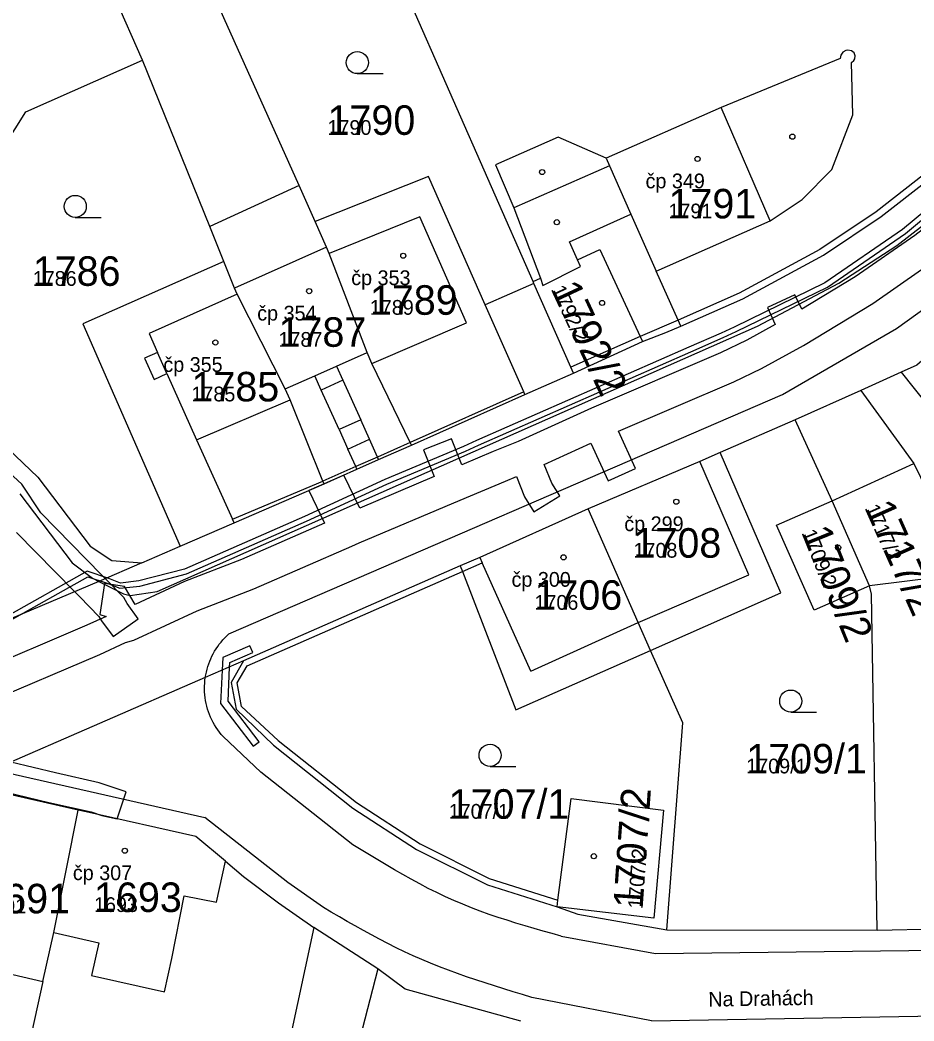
# Model space of a CAD drawing. Extents: x -763628 to -761565, y -976033 to -973833.
# Drawn here: x -762525.4 to -762464.8, y -975069 to -975001.2 of the extents above; entities that cross this region are included whole.
import ezdxf

# ---------------------------------------------------------------- set-up
doc = ezdxf.new("R2010")
doc.units = 0
for name, color, linetype in [('KN_cisla parcel 1000', 7, 'Continuous'), ('KN_cisla parcel 500', 7, 'Continuous'), ('KN_cisla popisna 500', 7, 'Continuous'), ('KN_hranice parcel', 7, 'Continuous'), ('KN_popisy', 7, 'Continuous'), ('KN_vecna bremena', 7, 'Continuous'), ('KN_vnitrni kresba parcel', 7, 'Continuous'), ('KN_znacky budov', 7, 'Continuous'), ('KN_znacky kultur', 7, 'Continuous')]:
    doc.layers.add(name, color=color, linetype=linetype)

msp = doc.modelspace()

# ---------------------------------------------------------------- linework, layer by layer
at = {"layer": 'KN_hranice parcel'}
for p, q in [((-762517.1, -975003.93), (-762523.87, -974988.55)), ((-762490.64, -975018.92), (-762501.97, -974993.16)), ((-762512.55, -975015.2), (-762517.1, -975003.93)), ((-762506.5, -975012.42), (-762512.55, -975015.2)), ((-762505.4, -975014.87), (-762506.5, -975012.42)), ((-762511.6, -975017.57), (-762512.55, -975015.2)), ((-762490.64, -975018.92), (-762490.15, -975018.71)), ((-762490.58, -975019.05), (-762490.64, -975018.92)), ((-762487.91, -975025.13), (-762483.23, -975022.98)), ((-762465.7, -975025.07), (-762468.44, -975026.31)), ((-762468.44, -975026.31), (-762472.88, -975028.3)), ((-762472.88, -975028.3), (-762477.97, -975030.52)), ((-762470.38, -975033.78), (-762472.88, -975028.3)), ((-762467.84, -975039.55), (-762470.38, -975033.78)), ((-762517.15, -975038), (-762514.55, -975036.87)), ((-762495.58, -975038.2), (-762510.26, -975044.64)), ((-762461.2, -975038.71), (-762467.84, -975039.55)), ((-762523.11, -975063.05), (-762521.46, -975054.75)), ((-762505.49, -975062.7), (-762510.94, -975087.94)), ((-762501.17, -975065.5), (-762505.49, -975062.7)), ((-762481.58, -975062.85), (-762467.32, -975062.87)), ((-762467.32, -975062.87), (-762452.41, -975062.54)), ((-762523.85, -975066.37), (-762523.11, -975063.05)), ((-762523.85, -975066.37), (-762527.5, -975082.74))]:
    msp.add_line(p, q, dxfattribs=at)
for points in [[(-762506.5, -975012.42), (-762513, -974997.92), (-762501.97, -974993.16)], [(-762480.64, -975021.95), (-762476.44, -975020.11), (-762470.96, -975017.13), (-762467.07, -975014.52), (-762463.89, -975012.05), (-762460.54, -975009.19), (-762458.45, -975006.67), (-762454.5, -975000.38)], [(-762469.83, -975003.81), (-762477.89, -975007.14), (-762485.7, -975010.56), (-762488.95, -975009.15), (-762493.19, -975011.01), (-762491.95, -975013.93), (-762490.15, -975018.71)], [(-762469.07, -975004.08), (-762468.906, -975003.949), (-762468.842, -975003.836), (-762468.816, -975003.627), (-762468.89, -975003.43), (-762469.079, -975003.295), (-762469.307, -975003.252), (-762469.453, -975003.276), (-762469.654, -975003.392), (-762469.788, -975003.582), (-762469.83, -975003.81)], [(-762534.93, -975023.19), (-762525.01, -975007.43), (-762517.1, -975003.93)], [(-762480.64, -975021.95), (-762480.82, -975021.54), (-762482.31, -975018.23), (-762474.57, -975014.82), (-762472.41, -975013.37), (-762470.39, -975011.34), (-762468.98, -975007.63), (-762469.07, -975004.08)], [(-762490.58, -975019.05), (-762493.89, -975020.51), (-762497.72, -975011.81), (-762505.4, -975014.87)], [(-762498.88, -975030.01), (-762498.97, -975029.83), (-762501.56, -975024.48), (-762501.89, -975023.74), (-762504.46, -975017.02), (-762504.63, -975016.6), (-762505.4, -975014.87)], [(-762490.15, -975018.71), (-762489.97, -975019.19), (-762487.42, -975017.92), (-762487.63, -975017.46), (-762486.13, -975016.76), (-762483.38, -975022.66), (-762483.23, -975022.98)], [(-762511.6, -975017.57), (-762521.15, -975021.79), (-762514.55, -975036.87)], [(-762504.8, -975032.64), (-762504.88, -975032.46), (-762507.1, -975026.94), (-762507.43, -975026.2), (-762510.68, -975019.79), (-762510.87, -975019.38), (-762511.6, -975017.57)], [(-762487.91, -975025.13), (-762488.09, -975024.72), (-762490.58, -975019.05)], [(-762458.55, -975019.31), (-762464.65, -975024.6), (-762465.7, -975025.07)], [(-762483.23, -975022.98), (-762481.65, -975022.39), (-762480.64, -975021.95)], [(-762534.93, -975023.19), (-762529.25, -975027.37), (-762524.19, -975032.19), (-762520.65, -975036.86), (-762519.19, -975037.83), (-762517.15, -975038)], [(-762498.88, -975030.01), (-762491.19, -975026.59), (-762487.91, -975025.13)], [(-762465.7, -975025.07), (-762460.23, -975031.94), (-762459.3, -975033.11), (-762458.98, -975033.52), (-762457.78, -975032.48), (-762451.59, -975027.12)], [(-762468.44, -975026.31), (-762464.84, -975031.25), (-762461.2, -975038.71)], [(-762504.8, -975032.64), (-762502.58, -975031.65), (-762501.11, -975030.99), (-762498.88, -975030.01)], [(-762477.97, -975030.52), (-762479.34, -975031.12), (-762486.91, -975034.34)], [(-762482.69, -975043.92), (-762473.86, -975040.03), (-762477.97, -975030.52)], [(-762514.55, -975036.87), (-762510.89, -975035.28), (-762504.8, -975032.64)], [(-762486.91, -975034.34), (-762494.25, -975037.62), (-762495.58, -975038.2)], [(-762482.69, -975043.92), (-762483.53, -975042.04), (-762486.91, -975034.34)], [(-762467.84, -975039.55), (-762471.6, -975041.2), (-762474.14, -975035.44), (-762470.38, -975033.78)], [(-762517.15, -975038), (-762520.07, -975039.25), (-762525.98, -975041.77), (-762528.89, -975043.05)], [(-762495.58, -975038.2), (-762495.42, -975038.57), (-762491.81, -975047.94), (-762482.69, -975043.92)], [(-762467.32, -975062.87), (-762467.71, -975040.11), (-762467.84, -975039.55)], [(-762481.58, -975062.85), (-762480.49, -975048.83), (-762482.69, -975043.92)], [(-762510.26, -975044.64), (-762512.85, -975045.76), (-762527.2, -975052), (-762529.39, -975052.95)], [(-762510.26, -975044.64), (-762511.1, -975046.1), (-762510.76, -975047.9), (-762508.23, -975050.35), (-762502.86, -975054.62), (-762498.54, -975057.41), (-762493.74, -975059.82), (-762489.02, -975061.3), (-762487.6, -975061.79), (-762481.58, -975062.85)], [(-762521.46, -975054.75), (-762529.29, -975052.97), (-762529.39, -975052.95)], [(-762489.02, -975061.3), (-762488.96, -975060.85), (-762488.06, -975053.96), (-762481.8, -975054.75), (-762482.47, -975062.06), (-762489.02, -975061.3)], [(-762533.02, -975054.55), (-762533.31, -975056.34), (-762530.12, -975057), (-762531, -975061.31), (-762531.75, -975063.61), (-762527.39, -975064.54), (-762527.66, -975065.47), (-762523.85, -975066.37)], [(-762511.48, -975058.21), (-762513.48, -975056.53), (-762520.93, -975054.87), (-762521.46, -975054.75)], [(-762523.11, -975063.05), (-762520.07, -975063.73), (-762520.57, -975065.95), (-762515.62, -975067.05), (-762515.12, -975064.81), (-762514.28, -975060.55), (-762512.09, -975060.99), (-762511.48, -975058.21)], [(-762511.48, -975058.21), (-762510.25, -975059.24), (-762507.9, -975061.04), (-762505.49, -975062.7)], [(-762501.17, -975065.5), (-762502.4, -975070.31), (-762500.43, -975070.85), (-762501.58, -975075.02), (-762493.66, -975077.17)], [(-762491.47, -975069.04), (-762499.31, -975066.88), (-762501.17, -975065.5)]]:
    msp.add_lwpolyline(points, dxfattribs=at)
at = {"layer": 'KN_vecna bremena'}
for points in [[(-762447.96, -974992.32), (-762452.51, -975001.43), (-762454.75, -975004.97), (-762459.16, -975010.04), (-762465.61, -975015.4), (-762470.88, -975019.02), (-762477.02, -975022.01), (-762477.9, -975022.43), (-762480.09, -975023.37), (-762494.48, -975029.7), (-762495.36, -975030.1), (-762500.68, -975032.35), (-762506.13, -975034.84), (-762514.25, -975038.42), (-762517.35, -975039.22), (-762518.59, -975039.37), (-762519.38, -975039.05), (-762520.85, -975038.55), (-762526.38, -975041.67)], [(-762526.12, -975041.91), (-762520.81, -975038.93), (-762519.5, -975039.37), (-762518.63, -975039.71), (-762517.29, -975039.56), (-762514.13, -975038.74), (-762505.99, -975035.16), (-762500.54, -975032.67), (-762495.22, -975030.42), (-762494.34, -975030.02), (-762479.95, -975023.69), (-762477.76, -975022.73), (-762476.88, -975022.31), (-762470.7, -975019.32), (-762465.41, -975015.68), (-762458.92, -975010.28), (-762454.47, -975005.17), (-762452.21, -975001.59), (-762447.66, -974992.46)], [(-762451.11, -975001.14), (-762453.78, -975005.44), (-762456.48, -975008.62), (-762459.6, -975011.82), (-762464.78, -975015.8), (-762468.81, -975018.6), (-762472.44, -975020.8), (-762472.9, -975019.82), (-762474.76, -975020.68), (-762474.23, -975021.83), (-762476.16, -975022.89), (-762477.95, -975023.76), (-762486.68, -975027.5), (-762491.66, -975029.76), (-762493.35, -975030.45), (-762495.46, -975031.34), (-762496.16, -975029.58), (-762498.06, -975030.34), (-762497.35, -975032.15), (-762502.38, -975034.28), (-762503.46, -975032.04), (-762504.8, -975032.64), (-762505.83, -975033.08), (-762504.77, -975035.31)], [(-762527.76, -975047.49), (-762520, -975044.19), (-762518.25, -975043.39), (-762517.68, -975043.23), (-762513.39, -975041.24), (-762509.57, -975039.76), (-762502.93, -975036.87), (-762502.43, -975036.64), (-762495.59, -975033.74), (-762492.52, -975032.45), (-762491.77, -975032.14), (-762491.22, -975033.51), (-762490.58, -975034.54), (-762488.84, -975033.46), (-762489.38, -975032.58), (-762489.89, -975031.33), (-762486.72, -975029.89), (-762485.56, -975032.44), (-762483.7, -975031.6), (-762484.85, -975029.07), (-762477.05, -975025.72), (-762475.17, -975024.81), (-762472.33, -975023.26), (-762467.63, -975020.42), (-762464.33, -975018.12)], [(-762525.63, -975035.93), (-762521.7, -975039.94), (-762521.36, -975040.29), (-762520.06, -975041.62), (-762519.88, -975041.93), (-762519.1, -975042.98), (-762517.4, -975041.78), (-762518.14, -975040.75), (-762518.38, -975040.34), (-762519.63, -975039.06), (-762519.86, -975038.83), (-762523.99, -975034.61), (-762525.27, -975032.65), (-762530.21, -975028.14)], [(-762504.77, -975035.31), (-762510.39, -975037.76), (-762514.25, -975039.26), (-762517.59, -975040.81), (-762518.32, -975039.6), (-762519.67, -975039.4), (-762519.99, -975041.48), (-762519.57, -975041.62), (-762520.88, -975042.21), (-762528.6, -975045.51)], [(-762529.16, -975052.85), (-762523.45, -975054.22), (-762520.59, -975054.87), (-762519.86, -975055.11), (-762518.81, -975055.34), (-762518.2, -975053.5), (-762520.05, -975052.89), (-762522.99, -975052.22), (-762526.03, -975051.49)]]:
    msp.add_lwpolyline(points, dxfattribs=at)
msp.add_lwpolyline([(-762509.61, -975050.42), (-762509.21, -975050.12), (-762511.31, -975047.36), (-762511.2, -975045.05), (-762511.19, -975044.74), (-762509.64, -975044.07), (-762509.84, -975043.61), (-762511.67, -975044.4), (-762511.71, -975045.27), (-762511.81, -975047.52)], close=True, dxfattribs=at)
at = {"layer": 'KN_vnitrni kresba parcel'}
for p, q in [((-762474.57, -975014.82), (-762477.89, -975007.14)), ((-762485.7, -975010.56), (-762485.46, -975011.09)), ((-762485.46, -975011.09), (-762491.95, -975013.93)), ((-762485.46, -975011.09), (-762484.02, -975014.36)), ((-762464.19, -975011.7), (-762467.4, -975014.21)), ((-762498.31, -975014.55), (-762504.46, -975017.02)), ((-762495.15, -975021.73), (-762498.31, -975014.55)), ((-762488.17, -975016.23), (-762484.02, -975014.36)), ((-762484.02, -975014.36), (-762482.31, -975018.23)), ((-762467.4, -975014.21), (-762471.21, -975016.76)), ((-762466, -975016.49), (-762462.82, -975014.02)), ((-762504.63, -975016.6), (-762510.87, -975019.38)), ((-762487.63, -975017.46), (-762488.17, -975016.23)), ((-762469.92, -975019.04), (-762466, -975016.49)), ((-762471.21, -975016.76), (-762476.67, -975019.72)), ((-762466.01, -975022.1), (-762459.57, -975017.44)), ((-762475.44, -975021.95), (-762469.92, -975019.04)), ((-762510.68, -975019.79), (-762516.66, -975022.46)), ((-762476.67, -975019.72), (-762480.82, -975021.54)), ((-762491.27, -975026.4), (-762493.89, -975020.51)), ((-762516.11, -975039.93), (-762475.44, -975021.95)), ((-762501.56, -975024.48), (-762495.15, -975021.73)), ((-762480.82, -975021.54), (-762483.38, -975022.66)), ((-762473.75, -975026.58), (-762466.01, -975022.1)), ((-762516.66, -975022.46), (-762516.09, -975023.73)), ((-762483.38, -975022.66), (-762488.09, -975024.72)), ((-762516.09, -975023.73), (-762516.97, -975024.12)), ((-762516.97, -975024.12), (-762516.32, -975025.56)), ((-762515.45, -975025.17), (-762516.09, -975023.73)), ((-762503.95, -975024.66), (-762501.89, -975023.74)), ((-762505.43, -975025.32), (-762503.95, -975024.66)), ((-762503.95, -975024.66), (-762503.53, -975025.62)), ((-762516.32, -975025.56), (-762515.45, -975025.17)), ((-762515.45, -975025.17), (-762513.44, -975029.66)), ((-762507.43, -975026.2), (-762505.43, -975025.32)), ((-762505, -975026.28), (-762505.43, -975025.32)), ((-762503.53, -975025.62), (-762505, -975026.28)), ((-762503.53, -975025.62), (-762502.32, -975028.3)), ((-762511.26, -975042.81), (-762473.75, -975026.58)), ((-762503.79, -975028.96), (-762505, -975026.28)), ((-762491.27, -975026.4), (-762498.97, -975029.83)), ((-762491.19, -975026.59), (-762491.27, -975026.4)), ((-762513.44, -975029.66), (-762507.1, -975026.94)), ((-762502.32, -975028.3), (-762503.79, -975028.96)), ((-762501.73, -975029.62), (-762502.32, -975028.3)), ((-762503.79, -975028.96), (-762503.2, -975030.28)), ((-762513.44, -975029.66), (-762511.01, -975035.04)), ((-762503.2, -975030.28), (-762501.73, -975029.62)), ((-762502.66, -975031.47), (-762503.2, -975030.28)), ((-762501.19, -975030.82), (-762501.73, -975029.62)), ((-762498.97, -975029.83), (-762501.19, -975030.82)), ((-762501.19, -975030.82), (-762502.66, -975031.47)), ((-762501.11, -975030.99), (-762501.19, -975030.82)), ((-762502.66, -975031.47), (-762504.88, -975032.46)), ((-762502.58, -975031.65), (-762502.66, -975031.47)), ((-762476.02, -975038.81), (-762479.34, -975031.12)), ((-762470.38, -975033.78), (-762464.84, -975031.25)), ((-762511.01, -975035.04), (-762504.88, -975032.46)), ((-762525.42, -975033.32), (-762521.86, -975037.98)), ((-762510.89, -975035.28), (-762511.01, -975035.04)), ((-762494.25, -975037.62), (-762494.09, -975037.99)), ((-762521.86, -975037.98), (-762520.49, -975039.03)), ((-762495.42, -975038.57), (-762494.09, -975037.99)), ((-762490.79, -975045.32), (-762494.09, -975037.99)), ((-762520.49, -975039.03), (-762520.07, -975039.25)), ((-762510.01, -975044.97), (-762495.42, -975038.57)), ((-762483.53, -975042.04), (-762476.02, -975038.81)), ((-762520.07, -975039.25), (-762518.4, -975040.09)), ((-762518.4, -975040.09), (-762517.95, -975040.2)), ((-762517.95, -975040.2), (-762516.11, -975039.93)), ((-762490.79, -975045.32), (-762483.53, -975042.04)), ((-762510.69, -975046.13), (-762510.01, -975044.97)), ((-762510.39, -975047.73), (-762510.69, -975046.13)), ((-762510.39, -975047.73), (-762507.92, -975050.03)), ((-762509.09, -975052.17), (-762511.64, -975049.76)), ((-762507.92, -975050.03), (-762502.61, -975054.24)), ((-762527.2, -975052), (-762512.88, -975055.25)), ((-762502.85, -975057.1), (-762509.09, -975052.17)), ((-762502.61, -975054.24), (-762498.3, -975057.03)), ((-762507.26, -975059.66), (-762512.88, -975055.25)), ((-762498.3, -975057.03), (-762493.61, -975059.39)), ((-762493.61, -975059.39), (-762488.96, -975060.85)), ((-762504.85, -975061.35), (-762507.26, -975059.66)), ((-762488.74, -975063.29), (-762482.34, -975064.47)), ((-762482.34, -975064.47), (-762398.83, -975063.4)), ((-762482.63, -975069.03), (-762490.72, -975067.44)), ((-762482.63, -975069.03), (-762402.02, -975067.64))]:
    msp.add_line(p, q, dxfattribs=at)
for points in [[(-762512.85, -975045.76), (-762512.817, -975045.573), (-762512.778, -975045.387), (-762512.731, -975045.203), (-762512.678, -975045.021), (-762512.617, -975044.841), (-762512.55, -975044.664), (-762512.476, -975044.489), (-762512.396, -975044.317), (-762512.309, -975044.148), (-762512.216, -975043.983), (-762512.116, -975043.821), (-762512.011, -975043.663), (-762511.9, -975043.509), (-762511.782, -975043.36), (-762511.66, -975043.215), (-762511.532, -975043.075), (-762511.398, -975042.94), (-762511.26, -975042.81)], [(-762511.64, -975049.76), (-762511.768, -975049.612), (-762511.891, -975049.458), (-762512.007, -975049.3), (-762512.116, -975049.137), (-762512.22, -975048.97), (-762512.316, -975048.8), (-762512.405, -975048.625), (-762512.488, -975048.447), (-762512.563, -975048.266), (-762512.631, -975048.082), (-762512.691, -975047.895), (-762512.745, -975047.706), (-762512.79, -975047.515), (-762512.828, -975047.323), (-762512.858, -975047.129), (-762512.88, -975046.934), (-762512.895, -975046.738), (-762512.901, -975046.542), (-762512.9, -975046.346), (-762512.891, -975046.15), (-762512.875, -975045.955), (-762512.85, -975045.76)], [(-762488.74, -975063.29), (-762489.351, -975063.118), (-762489.969, -975062.943), (-762490.579, -975062.768), (-762491.188, -975062.589), (-762491.803, -975062.403), (-762492.408, -975062.213), (-762493.012, -975062.017), (-762493.62, -975061.809), (-762494.219, -975061.595), (-762494.814, -975061.37), (-762495.412, -975061.13), (-762496, -975060.88), (-762496.584, -975060.616), (-762497.17, -975060.336), (-762497.746, -975060.047), (-762498.319, -975059.748), (-762498.896, -975059.436), (-762499.463, -975059.118), (-762500.029, -975058.794), (-762500.599, -975058.46), (-762501.162, -975058.125), (-762501.723, -975057.787), (-762502.29, -975057.442), (-762502.85, -975057.1)], [(-762490.72, -975067.44), (-762491.355, -975067.248), (-762491.998, -975067.052), (-762492.631, -975066.857), (-762493.263, -975066.659), (-762493.899, -975066.456), (-762494.524, -975066.251), (-762495.145, -975066.041), (-762495.769, -975065.822), (-762496.38, -975065.6), (-762496.985, -975065.369), (-762497.59, -975065.128), (-762498.18, -975064.88), (-762498.762, -975064.622), (-762499.344, -975064.352), (-762499.912, -975064.077), (-762500.474, -975063.794), (-762501.037, -975063.501), (-762501.589, -975063.206), (-762502.137, -975062.906), (-762502.687, -975062.597), (-762503.229, -975062.289), (-762503.768, -975061.979), (-762504.313, -975061.663), (-762504.85, -975061.35)]]:
    msp.add_lwpolyline(points, dxfattribs=at)
at = {"layer": 'KN_znacky budov'}
for centre in [(-762473.077, -975009.109), (-762479.497, -975010.619), (-762490.027, -975011.509), (-762489.037, -975014.909), (-762499.437, -975017.179), (-762505.807, -975019.579), (-762485.967, -975020.379), (-762512.167, -975023.059), (-762480.937, -975033.849), (-762469.977, -975036.959), (-762488.577, -975037.619), (-762518.297, -975057.499), (-762486.527, -975057.869)]:
    msp.add_circle(centre, 0.175, dxfattribs=at)
at = {"layer": 'KN_znacky kultur'}
for p, q in [((-762502.553, -975004.84), (-762500.803, -975004.84)), ((-762521.663, -975014.59), (-762519.913, -975014.59)), ((-762473.183, -975048.11), (-762471.433, -975048.11)), ((-762493.553, -975051.78), (-762491.803, -975051.78))]:
    msp.add_line(p, q, dxfattribs=at)
for centre in [(-762502.553, -975004.09), (-762521.663, -975013.84), (-762473.183, -975047.36), (-762493.553, -975051.03)]:
    msp.add_circle(centre, 0.75, dxfattribs=at)

# ---------------------------------------------------------------- texts
at = {"layer": 'KN_cisla parcel 1000'}
for s, p in [('1790', (-762504.57, -975008.99)), ('1791', (-762481.47, -975014.65)), ('1786', (-762524.54, -975019.22)), ('1789', (-762501.7, -975021.18)), ('1787', (-762507.89, -975023.35)), ('1785', (-762513.79, -975027.05)), ('1708', (-762483.84, -975037.64)), ('1706', (-762490.55, -975041.17)), ('1709/1', (-762476.2, -975052.26)), ('1707/1', (-762496.36, -975055.33)), ('1691', (-762527.96, -975061.74)), ('1693', (-762520.39, -975061.65))]:
    msp.add_text(s, height=2, dxfattribs=at).set_placement(p)
for s, rotation, p in [('1792/2', 295, (-762489.448, -975019.452)), ('1717/2', 294, (-762468.191, -975034.28)), ('1709/2', 292, (-762472.469, -975035.951)), ('1707/2', 86, (-762483.222, -975061.459))]:
    msp.add_text(s, height=2, rotation=rotation, dxfattribs=at).set_placement(p)
at = {"layer": 'KN_cisla parcel 500'}
for s, p in [('1790', (-762504.57, -975008.99)), ('1791', (-762481.47, -975014.65)), ('1786', (-762524.54, -975019.22)), ('1789', (-762501.7, -975021.18)), ('1787', (-762507.89, -975023.35)), ('1785', (-762513.79, -975027.05)), ('1708', (-762483.84, -975037.64)), ('1706', (-762490.55, -975041.17)), ('1709/1', (-762476.2, -975052.26)), ('1707/1', (-762496.36, -975055.33)), ('1691', (-762527.96, -975061.74)), ('1693', (-762520.39, -975061.65))]:
    msp.add_text(s, height=1, dxfattribs=at).set_placement(p)
for s, rotation, p in [('1792/2', 295, (-762489.448, -975019.452)), ('1717/2', 294, (-762468.191, -975034.28)), ('1709/2', 292, (-762472.469, -975035.951)), ('1707/2', 86, (-762483.222, -975061.459))]:
    msp.add_text(s, height=1, rotation=rotation, dxfattribs=at).set_placement(p)
at = {"layer": 'KN_cisla popisna 500'}
for s, p in [('čp 349', (-762483.021, -975012.611)), ('čp 353', (-762502.961, -975019.171)), ('čp 354', (-762509.331, -975021.571)), ('čp 355', (-762515.691, -975025.051)), ('čp 299', (-762484.461, -975035.841)), ('čp 300', (-762492.101, -975039.611)), ('čp 307', (-762521.821, -975059.491))]:
    msp.add_text(s, height=1, dxfattribs=at).set_placement(p)
at = {"layer": 'KN_popisy'}
msp.add_text('Na Drahách', height=1, rotation=1, dxfattribs=at).set_placement((-762478.762, -975068.068))

doc.saveas('drawing.dxf')
